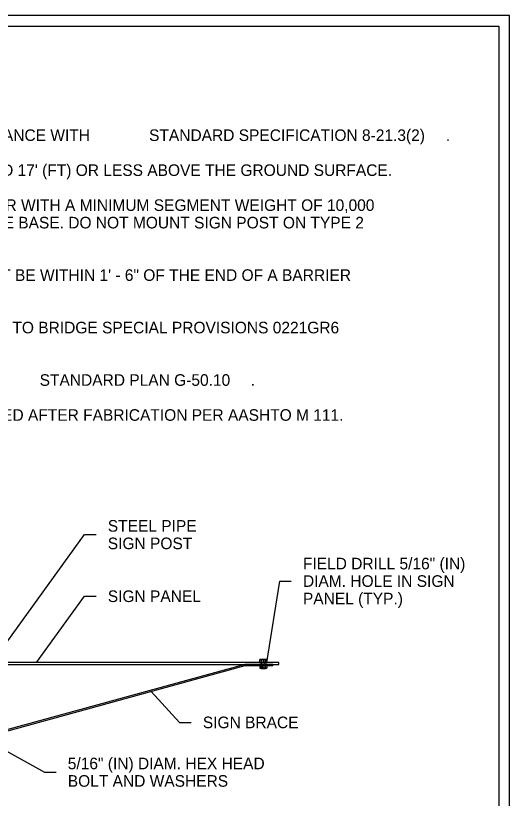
# Model space of a CAD drawing. Extents: x 99988 to 100172, y 99995 to 100047.
# Drawn here: x 100012.834 to 100015.812, y 100005.713 to 100010.437 of the extents above; entities that cross this region are included whole.
import ezdxf

# ---------------------------------------------------------------- set-up
doc = ezdxf.new("R2010")
doc.units = 0
for name, color, linetype in [('Level 15', 7, 'Continuous'), ('Level 20', 7, 'Continuous'), ('Level 3', 7, 'Continuous'), ('SH_GI_PlotLimits', 7, 'Continuous'), ('SH_GI_SheetBorder', 7, 'Continuous')]:
    doc.layers.add(name, color=color, linetype=linetype)

msp = doc.modelspace()

# ---------------------------------------------------------------- linework, layer by layer
at = {"layer": 'Level 15'}
for points in [[(100012.623, 100006.4409), (100013.2497, 100007.3048), (100013.3197, 100007.3048)], [(100014.3489, 100006.5332), (100014.4271, 100007.0245), (100014.4971, 100007.0245)], [(100012.9589, 100006.532), (100013.2497, 100006.9329), (100013.3197, 100006.9329)], [(100013.6519, 100006.3588), (100013.8233, 100006.1713), (100013.8933, 100006.1713)], [(100012.576, 100006.1096), (100013.0083, 100005.8707), (100013.0783, 100005.8707)]]:
    msp.add_lwpolyline(points, dxfattribs=at)
at = {"layer": 'Level 3'}
for p, q in [((100014.4213, 100006.532), (100010.6328, 100006.532)), ((100010.6328, 100006.5212), (100014.4213, 100006.5212)), ((100014.2169, 100006.5212), (100014.3847, 100006.5212)), ((100014.3847, 100006.5212), (100014.2169, 100006.5212)), ((100014.2169, 100006.5212), (100014.2169, 100006.5212)), ((100014.2169, 100006.5212), (100014.2169, 100006.5212)), ((100014.3847, 100006.5145), (100014.218, 100006.5145)), ((100014.218, 100006.5145), (100014.218, 100006.5145)), ((100014.218, 100006.5145), (100014.3847, 100006.5145)), ((100014.218, 100006.5145), (100014.218, 100006.5145)), ((100014.3142, 100006.5512), (100014.3073, 100006.55)), ((100014.3177, 100006.55), (100014.3073, 100006.55)), ((100014.3073, 100006.55), (100014.3177, 100006.55)), ((100014.3073, 100006.5332), (100014.3073, 100006.55)), ((100014.3073, 100006.5332), (100014.3177, 100006.5332)), ((100014.3177, 100006.5332), (100014.3073, 100006.5332)), ((100014.3073, 100006.5332), (100014.3142, 100006.532)), ((100014.3073, 100006.5153), (100014.3142, 100006.5165)), ((100014.3073, 100006.5153), (100014.3177, 100006.5153)), ((100014.3177, 100006.5153), (100014.3073, 100006.5153)), ((100014.3073, 100006.5153), (100014.3073, 100006.4985)), ((100014.3177, 100006.5512), (100014.3142, 100006.5512)), ((100014.3142, 100006.5512), (100014.3177, 100006.5512)), ((100014.3177, 100006.532), (100014.3142, 100006.532)), ((100014.3142, 100006.532), (100014.3177, 100006.532)), ((100014.3177, 100006.5165), (100014.3142, 100006.5165)), ((100014.3142, 100006.5165), (100014.3177, 100006.5165)), ((100014.3161, 100006.5512), (100014.3177, 100006.5512)), ((100014.3161, 100006.5512), (100014.3161, 100006.532)), ((100014.3161, 100006.532), (100014.3177, 100006.532)), ((100014.3161, 100006.5165), (100014.3177, 100006.5165)), ((100014.3161, 100006.4973), (100014.3161, 100006.5165)), ((100014.3173, 100006.532), (100014.3392, 100006.532)), ((100014.3173, 100006.5165), (100014.3173, 100006.532)), ((100014.3173, 100006.5165), (100014.3392, 100006.5165)), ((100014.3211, 100006.5512), (100014.3177, 100006.5512)), ((100014.3177, 100006.5512), (100014.3211, 100006.5512)), ((100014.3177, 100006.5512), (100014.3281, 100006.5512)), ((100014.3177, 100006.5512), (100014.3281, 100006.5512)), ((100014.3211, 100006.5512), (100014.3177, 100006.55)), ((100014.3177, 100006.55), (100014.3211, 100006.5512)), ((100014.3177, 100006.55), (100014.3385, 100006.55)), ((100014.3385, 100006.55), (100014.3177, 100006.55)), ((100014.3177, 100006.5332), (100014.3177, 100006.55)), ((100014.3177, 100006.5332), (100014.3177, 100006.55)), ((100014.3385, 100006.5332), (100014.3177, 100006.5332)), ((100014.3177, 100006.5332), (100014.3385, 100006.5332)), ((100014.3177, 100006.5332), (100014.3211, 100006.532)), ((100014.3211, 100006.532), (100014.3177, 100006.5332)), ((100014.3211, 100006.532), (100014.3177, 100006.532)), ((100014.3177, 100006.532), (100014.3211, 100006.532)), ((100014.3177, 100006.532), (100014.3281, 100006.532)), ((100014.3177, 100006.532), (100014.3281, 100006.532)), ((100014.3211, 100006.5165), (100014.3177, 100006.5165)), ((100014.3177, 100006.5165), (100014.3211, 100006.5165)), ((100014.3177, 100006.5165), (100014.3281, 100006.5165)), ((100014.3177, 100006.5165), (100014.3281, 100006.5165)), ((100014.3177, 100006.5153), (100014.3211, 100006.5165)), ((100014.3211, 100006.5165), (100014.3177, 100006.5153)), ((100014.3385, 100006.5153), (100014.3177, 100006.5153)), ((100014.3177, 100006.5153), (100014.3385, 100006.5153)), ((100014.3177, 100006.5153), (100014.3177, 100006.4985)), ((100014.3177, 100006.5153), (100014.3177, 100006.4985)), ((100014.3211, 100006.5512), (100014.3281, 100006.5512)), ((100014.3281, 100006.5512), (100014.3211, 100006.5512)), ((100014.3281, 100006.5512), (100014.335, 100006.5512)), ((100014.335, 100006.5512), (100014.3281, 100006.5512)), ((100014.3281, 100006.5512), (100014.3385, 100006.5512)), ((100014.3281, 100006.5512), (100014.3385, 100006.5512)), ((100014.3281, 100006.5512), (100014.3281, 100006.532)), ((100014.335, 100006.532), (100014.3281, 100006.532)), ((100014.3281, 100006.532), (100014.335, 100006.532)), ((100014.3281, 100006.532), (100014.3385, 100006.532)), ((100014.3281, 100006.532), (100014.3385, 100006.532)), ((100014.335, 100006.5165), (100014.3281, 100006.5165)), ((100014.3281, 100006.5165), (100014.335, 100006.5165)), ((100014.3281, 100006.5165), (100014.3385, 100006.5165)), ((100014.3281, 100006.5165), (100014.3385, 100006.5165)), ((100014.3281, 100006.4973), (100014.3281, 100006.5165)), ((100014.335, 100006.5512), (100014.3385, 100006.5512)), ((100014.3385, 100006.5512), (100014.335, 100006.5512)), ((100014.335, 100006.5512), (100014.3385, 100006.55)), ((100014.335, 100006.5512), (100014.3385, 100006.55)), ((100014.3385, 100006.5332), (100014.335, 100006.532)), ((100014.3385, 100006.5332), (100014.335, 100006.532)), ((100014.3385, 100006.532), (100014.335, 100006.532)), ((100014.335, 100006.532), (100014.3385, 100006.532)), ((100014.3385, 100006.5165), (100014.335, 100006.5165)), ((100014.335, 100006.5165), (100014.3385, 100006.5165)), ((100014.3385, 100006.5153), (100014.335, 100006.5165)), ((100014.3385, 100006.5153), (100014.335, 100006.5165)), ((100014.3385, 100006.5512), (100014.3419, 100006.5512)), ((100014.3419, 100006.5512), (100014.3385, 100006.5512)), ((100014.3385, 100006.5512), (100014.3401, 100006.5512)), ((100014.3385, 100006.55), (100014.3489, 100006.55)), ((100014.3489, 100006.55), (100014.3385, 100006.55)), ((100014.3385, 100006.5332), (100014.3385, 100006.55)), ((100014.3385, 100006.5332), (100014.3385, 100006.55)), ((100014.3489, 100006.5332), (100014.3385, 100006.5332)), ((100014.3385, 100006.5332), (100014.3489, 100006.5332)), ((100014.3419, 100006.532), (100014.3385, 100006.532)), ((100014.3385, 100006.532), (100014.3419, 100006.532)), ((100014.3385, 100006.532), (100014.3401, 100006.532)), ((100014.3419, 100006.5165), (100014.3385, 100006.5165)), ((100014.3385, 100006.5165), (100014.3419, 100006.5165)), ((100014.3385, 100006.5165), (100014.3401, 100006.5165)), ((100014.3489, 100006.5153), (100014.3385, 100006.5153)), ((100014.3385, 100006.5153), (100014.3489, 100006.5153)), ((100014.3385, 100006.5153), (100014.3385, 100006.4985)), ((100014.3385, 100006.5153), (100014.3385, 100006.4985)), ((100014.3392, 100006.5165), (100014.3392, 100006.532)), ((100014.3401, 100006.5512), (100014.3401, 100006.532)), ((100014.3401, 100006.4973), (100014.3401, 100006.5165)), ((100014.3419, 100006.5512), (100014.3489, 100006.55)), ((100014.3489, 100006.5332), (100014.3419, 100006.532)), ((100014.3489, 100006.5153), (100014.3419, 100006.5165)), ((100014.3489, 100006.5332), (100014.3489, 100006.55)), ((100014.3489, 100006.5153), (100014.3489, 100006.4985)), ((100014.3847, 100006.5212), (100014.3847, 100006.5212)), ((100014.3847, 100006.5212), (100014.3847, 100006.5145)), ((100014.3847, 100006.5145), (100014.3847, 100006.5212)), ((100014.3847, 100006.5212), (100014.3847, 100006.5212)), ((100014.3847, 100006.5212), (100014.3847, 100006.5212)), ((100014.3847, 100006.5145), (100014.3847, 100006.5145)), ((100014.3847, 100006.5145), (100014.3847, 100006.5145)), ((100014.3847, 100006.5145), (100014.3847, 100006.5145)), ((100014.4213, 100006.5212), (100014.4213, 100006.532)), ((100014.3177, 100006.4985), (100014.3073, 100006.4985)), ((100014.3073, 100006.4985), (100014.3177, 100006.4985)), ((100014.3142, 100006.4973), (100014.3073, 100006.4985)), ((100014.3177, 100006.4973), (100014.3142, 100006.4973)), ((100014.3142, 100006.4973), (100014.3177, 100006.4973)), ((100014.3161, 100006.4973), (100014.3177, 100006.4973)), ((100014.3177, 100006.4985), (100014.3385, 100006.4985)), ((100014.3385, 100006.4985), (100014.3177, 100006.4985)), ((100014.3211, 100006.4973), (100014.3177, 100006.4985)), ((100014.3177, 100006.4985), (100014.3211, 100006.4973)), ((100014.3211, 100006.4973), (100014.3177, 100006.4973)), ((100014.3177, 100006.4973), (100014.3211, 100006.4973)), ((100014.3177, 100006.4973), (100014.3281, 100006.4973)), ((100014.3177, 100006.4973), (100014.3281, 100006.4973)), ((100014.3211, 100006.4973), (100014.3281, 100006.4973)), ((100014.3281, 100006.4973), (100014.3211, 100006.4973)), ((100014.3281, 100006.4973), (100014.335, 100006.4973)), ((100014.335, 100006.4973), (100014.3281, 100006.4973)), ((100014.3281, 100006.4973), (100014.3385, 100006.4973)), ((100014.3281, 100006.4973), (100014.3385, 100006.4973)), ((100014.335, 100006.4973), (100014.3385, 100006.4985)), ((100014.335, 100006.4973), (100014.3385, 100006.4985)), ((100014.335, 100006.4973), (100014.3385, 100006.4973)), ((100014.3385, 100006.4973), (100014.335, 100006.4973)), ((100014.3385, 100006.4985), (100014.3489, 100006.4985)), ((100014.3489, 100006.4985), (100014.3385, 100006.4985)), ((100014.3385, 100006.4973), (100014.3419, 100006.4973)), ((100014.3419, 100006.4973), (100014.3385, 100006.4973)), ((100014.3385, 100006.4973), (100014.3401, 100006.4973)), ((100014.3419, 100006.4973), (100014.3489, 100006.4985))]:
    msp.add_line(p, q, dxfattribs=at)
msp.add_lwpolyline([(100012.7734, 100006.1171), (100014.218, 100006.5145), (100014.3847, 100006.5145), (100014.3847, 100006.5212), (100014.2169, 100006.5212), (100012.7734, 100006.1235)], dxfattribs=at)
msp.add_lwpolyline([(100012.7734, 100006.1171), (100014.218, 100006.5145), (100014.3847, 100006.5145), (100014.3847, 100006.5212), (100014.2169, 100006.5212), (100012.7734, 100006.1235)], dxfattribs=at)
at = {"layer": 'SH_GI_PlotLimits'}
msp.add_lwpolyline([(99999.3125, 99999.9375), (100015.8125, 99999.9375), (100015.8125, 100010.4375), (99999.3125, 100010.4375)], close=True, dxfattribs=at)
at = {"layer": 'SH_GI_SheetBorder'}
for p, q in [((100000, 100010.375), (100015.75, 100010.375)), ((100015.75, 100010.375), (100015.75, 100000))]:
    msp.add_line(p, q, dxfattribs=at)

# ---------------------------------------------------------------- texts
at = {"layer": 'Level 20'}
for s, p in [('PLACEMENT OF SIGN SHALL BE IN ACCORDANCE WITH ', (100010.7493, 100009.6809)), ('STANDARD SPECIFICATION 8-21.3(2)', (100013.6388, 100009.6809)), ('.', (100015.4295, 100009.6809)), ("CENTER OF SIGN PANEL SHALL BE LOCATED 17' (FT) OR LESS ABOVE THE GROUND SURFACE.", (100010.7493, 100009.4698)), ('SIGN POST SHALL BE MOUNTED ON BARRIER WITH A MINIMUM SEGMENT WEIGHT OF 10,000 ', (100010.7493, 100009.2586)), ('LBS. AND A MINIMUM WIDTH OF 2\' - 0" AT THE BASE. DO NOT MOUNT SIGN POST ON TYPE 2 ', (100010.7493, 100009.1531)), ('SADDLE MOUNT ANCHOR BOLTS SHALL NOT BE WITHIN 1\' - 6" OF THE END OF A BARRIER ', (100010.7493, 100008.8364)), ('RESIN BONDED ANCHORS SHALL CONFORM TO BRIDGE SPECIAL PROVISIONS 0221GR6 ', (100010.7493, 100008.5197)), ('STANDARD PLAN G-50.10', (100012.9787, 100008.203)), ('.', (100014.2517, 100008.203)), ('SIGN POST ASSEMBLY SHALL BE GALVANIZED AFTER FABRICATION PER AASHTO M 111.', (100010.7493, 100007.9919)), ('SIGN PANEL', (100013.3897, 100006.8979))]:
    msp.add_text(s, height=0.07, dxfattribs=at).set_placement(p)
for s, p in [('STEEL PIPE', (100013.3897, 100007.3226)), ('SIGN POST', (100013.3897, 100007.217)), ('FIELD DRILL 5/16" (IN)', (100014.5671, 100007.095)), ('DIAM. HOLE IN SIGN', (100014.5671, 100006.9895)), ('PANEL (TYP.)', (100014.5671, 100006.8839)), ('SIGN BRACE', (100013.9633, 100006.1363)), ('5/16" (IN) DIAM. HEX HEAD', (100013.1483, 100005.8885)), ('BOLT AND WASHERS', (100013.1483, 100005.7829))]:
    msp.add_text(s, height=0.07, rotation=360, dxfattribs=at).set_placement(p)

doc.saveas('drawing.dxf')
